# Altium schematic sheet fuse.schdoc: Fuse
size A4; Organization: Altium Limited; Address1: L3, 12a Rodborough Rd; Address2: Frenchs Forest; Address3: NSW; Address4: Australia 2086; DocumentNumber: 1; SheetNumber: 1; SheetTotal: 1
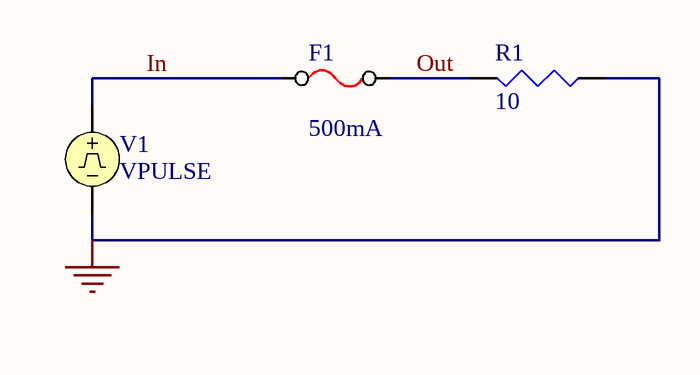
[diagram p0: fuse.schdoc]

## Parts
F1  500mA
R1  10
V1  VPULSE

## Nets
GND: R1.2(BOT) V1.2
In: F1.1 V1.1
Out: F1.2 R1.1(TOP)

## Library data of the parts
F1 = FUSE
R1 = RES: Resistor
V1 = VPULSE: Pulse Voltage Source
